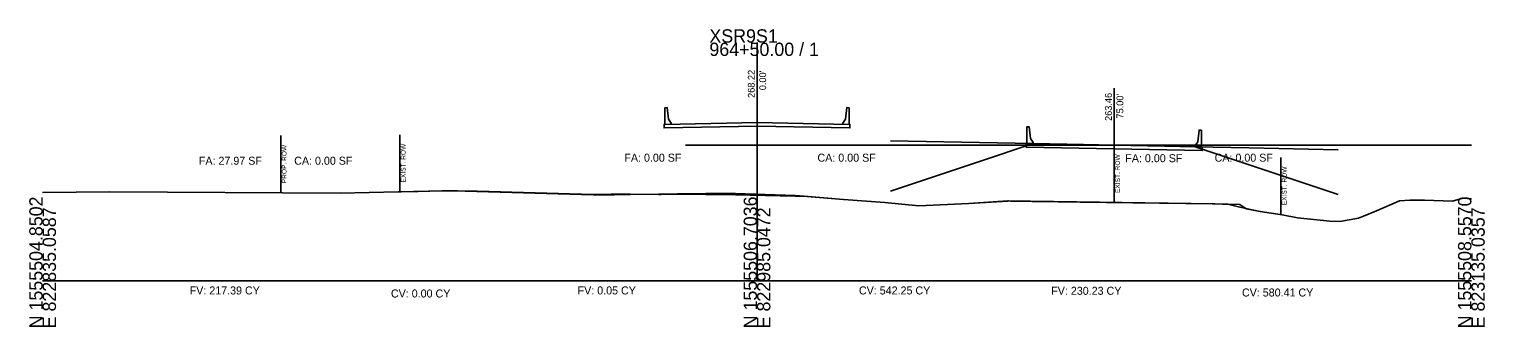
# Model space of a CAD drawing. Extents: x -26 to 823017, y -16 to 1558356.
# Drawn here: x 997.2 to 1302.8, y 3990.3 to 4052.8 of the extents above; entities that cross this region are included whole.
import ezdxf

# ---------------------------------------------------------------- set-up
doc = ezdxf.new("R2010")
doc.units = 0
for name, color, linetype in [('CONST_LV3', 7, 'Continuous'), ('Draft_XS_Grid', 7, 'Continuous'), ('DTM_TEMP_DROP', 7, 'Continuous'), ('DTM_X_GROUND', 7, 'Continuous'), ('XS_CELL', 7, 'Continuous'), ('XS_P_CONCRETE', 7, 'Continuous'), ('XS_P_ROW', 7, 'Continuous'), ('XS_P_TX_CLEARZONE', 7, 'Continuous'), ('XS_SHEET_EW_TX_AREA', 7, 'Continuous'), ('XS_SHEET_EW_TX_VOLUME', 7, 'Continuous'), ('XS_X_ROW', 7, 'Continuous')]:
    doc.layers.add(name, color=color, linetype=linetype)

msp = doc.modelspace()

# ---------------------------------------------------------------- linework, layer by layer
at = {"layer": 'CONST_LV3'}
for points in [[(1178, 4029.4), (1196.69, 4029.03), (1208, 4028.8), (1218.59, 4028.59), (1225, 4028.46), (1235.59, 4028.25), (1242, 4028.12), (1253.31, 4027.9), (1272, 4027.52)], [(1135, 4028.46), (1270.69, 4028.46), (1300, 4028.46)], [(1178, 4018.8), (1196.69, 4025.03), (1208, 4028.8), (1218.59, 4028.59), (1225, 4028.46), (1235.59, 4028.25), (1242, 4028.12), (1253.31, 4024.35), (1272, 4018.12)], [(1000, 4018.55), (1014.1, 4018.69), (1062.49, 4018.4), (1074.65, 4018.64), (1075.26, 4018.66), (1078.83, 4018.75), (1083.81, 4018.89), (1084.26, 4018.9), (1085.24, 4018.88), (1085.42, 4018.88), (1087.17, 4018.85), (1088.71, 4018.82), (1091.26, 4018.75), (1115.61, 4018.02), (1116.22, 4018.03), (1119.39, 4018.07), (1120.02, 4018.07), (1123.35, 4018.11), (1129.29, 4018.2), (1129.91, 4018.2), (1133.34, 4018.23), (1139.25, 4018.32), (1139.85, 4018.32), (1143.34, 4018.35), (1145.45, 4018.29), (1158.01, 4017.92), (1159.9, 4017.75), (1168.15, 4017.05), (1176.81, 4016.42), (1183.98, 4015.75), (1194.49, 4016.24), (1199.14, 4016.53), (1202.6, 4016.73), (1202.79, 4016.75), (1203.23, 4016.74), (1203.92, 4016.73), (1204.53, 4016.72), (1206.18, 4016.7), (1207.81, 4016.67), (1208.62, 4016.66), (1211.26, 4016.62), (1213.18, 4016.6), (1213.94, 4016.58), (1216.27, 4016.55), (1217.83, 4016.53), (1245.57, 4016.13), (1246.01, 4016.12), (1246.12, 4016.12), (1247.77, 4016.09), (1247.89, 4016.08), (1248.84, 4016.07), (1251.36, 4015.48), (1252.69, 4015.17), (1253.99, 4014.86), (1255.67, 4014.57), (1260.28, 4013.82), (1263.51, 4013.2), (1270.27, 4012.54), (1272.39, 4012.44), (1276.27, 4013.17), (1277.36, 4013.55), (1280.07, 4014.71), (1284.92, 4016.77), (1287.11, 4016.92), (1290.19, 4016.92), (1296.02, 4016.73), (1298.18, 4017.32), (1300, 4017.17)]]:
    msp.add_lwpolyline(points, dxfattribs=at)
at = {"layer": 'DTM_X_GROUND'}
for points in [[(1000, 4018.55), (1014.1, 4018.69), (1062.49, 4018.4), (1074.65, 4018.64), (1084.26, 4018.9), (1088.71, 4018.82), (1115.61, 4018.02), (1119.39, 4018.07), (1123.35, 4018.11), (1129.29, 4018.2), (1133.34, 4018.23), (1139.25, 4018.32), (1143.34, 4018.35), (1158.01, 4017.92), (1168.15, 4017.05), (1176.81, 4016.42), (1183.98, 4015.75), (1194.49, 4016.24), (1202.6, 4016.75), (1246.01, 4016.12), (1251.36, 4016.02), (1252.69, 4015.09), (1255.67, 4014.57), (1260.28, 4013.82), (1263.51, 4013.2), (1270.27, 4012.54), (1272.39, 4012.44), (1276.27, 4013.17), (1277.36, 4013.55), (1280.07, 4014.71), (1284.92, 4016.77), (1287.11, 4016.92), (1290.19, 4016.92), (1296.02, 4016.73), (1298.18, 4017.32), (1300, 4017.17)], [(1000, 4018.55), (1014.1, 4018.69), (1062.49, 4018.4), (1074.65, 4018.64), (1084.26, 4018.9), (1088.71, 4018.82), (1115.61, 4018.02), (1119.39, 4018.07), (1123.35, 4018.11), (1129.29, 4018.2), (1133.34, 4018.23), (1139.25, 4018.32), (1143.34, 4018.35), (1158.01, 4017.92), (1168.15, 4017.05), (1176.81, 4016.42), (1183.98, 4015.75), (1194.49, 4016.24), (1199.14, 4016.53), (1202.6, 4016.73), (1202.79, 4016.75), (1203.23, 4016.74), (1203.92, 4016.73), (1204.53, 4016.72), (1206.18, 4016.7), (1207.81, 4016.67), (1208.62, 4016.66), (1211.26, 4016.62), (1213.18, 4016.6), (1213.94, 4016.58), (1216.27, 4016.55), (1217.83, 4016.53), (1245.57, 4016.13), (1246.01, 4016.12), (1246.12, 4016.12), (1247.77, 4016.09), (1247.89, 4016.08), (1248.84, 4016.07), (1251.36, 4015.48), (1252.69, 4015.17), (1253.99, 4014.86), (1255.67, 4014.57), (1260.28, 4013.82), (1263.51, 4013.2), (1270.27, 4012.54), (1272.39, 4012.44), (1276.27, 4013.17), (1277.36, 4013.55), (1280.07, 4014.71), (1284.92, 4016.77), (1287.11, 4016.92), (1290.19, 4016.92), (1296.02, 4016.73), (1298.18, 4017.32), (1300, 4017.17)], [(1000, 4018.55), (1014.1, 4018.69), (1062.49, 4018.4), (1074.65, 4018.64), (1075.26, 4018.66), (1078.83, 4018.75), (1083.81, 4018.85), (1084.26, 4018.85), (1085.24, 4018.85), (1085.42, 4018.88), (1087.17, 4018.86), (1088.71, 4018.84), (1091.26, 4018.81), (1115.61, 4018.14), (1116.22, 4018.13), (1119.39, 4018.16), (1120.02, 4018.16), (1123.35, 4018.19), (1129.29, 4018.12), (1129.91, 4018.12), (1133.34, 4018.15), (1139.25, 4018.08), (1139.85, 4018.07), (1143.34, 4018.1), (1145.45, 4018.07), (1158.01, 4017.78), (1159.9, 4017.75), (1168.15, 4017.05), (1176.81, 4016.42), (1183.98, 4015.75), (1194.49, 4016.24), (1199.14, 4016.53), (1202.6, 4016.73), (1202.79, 4016.75), (1203.23, 4016.74), (1203.92, 4016.73), (1204.53, 4016.72), (1206.18, 4016.7), (1207.81, 4016.67), (1208.62, 4016.66), (1211.26, 4016.62), (1213.18, 4016.6), (1213.94, 4016.58), (1216.27, 4016.55), (1217.83, 4016.53), (1245.57, 4016.13), (1246.01, 4016.12), (1246.12, 4016.12), (1247.77, 4016.09), (1247.89, 4016.08), (1248.84, 4016.07), (1251.36, 4015.48), (1252.69, 4015.17), (1253.99, 4014.86), (1255.67, 4014.57), (1260.28, 4013.82), (1263.51, 4013.2), (1270.27, 4012.54), (1272.39, 4012.44), (1276.27, 4013.17), (1277.36, 4013.55), (1280.07, 4014.71), (1284.92, 4016.77), (1287.11, 4016.92), (1290.19, 4016.92), (1296.02, 4016.73), (1298.18, 4017.32), (1300, 4017.17)]]:
    msp.add_lwpolyline(points, dxfattribs=at)
at = {"layer": 'XS_CELL'}
for p, q in [((1150, 4000), (1150, 4050)), ((1000, 4000), (1150, 4000)), ((1150, 4000), (1300, 4000))]:
    msp.add_line(p, q, dxfattribs=at)
at = {"layer": 'XS_P_CONCRETE'}
for points in [[(1132, 4032.86), (1132, 4033.11), (1131.42, 4033.94), (1131.17, 4036.36), (1130.67, 4036.33), (1130.67, 4032.83), (1132, 4032.86)], [(1168, 4032.86), (1168, 4033.11), (1168.58, 4033.94), (1168.83, 4036.36), (1169.33, 4036.33), (1169.33, 4032.83), (1168, 4032.86)], [(1150, 4033.22), (1169.33, 4032.83), (1169.5, 4032.83), (1169.5, 4032.08), (1150, 4032.47), (1130.5, 4032.08), (1130.5, 4032.83), (1130.67, 4032.83), (1150, 4033.22)], [(1206.67, 4028.83), (1206.67, 4032.33), (1207.17, 4032.3), (1207.42, 4029.88), (1208, 4029.05), (1208, 4028.8), (1206.67, 4028.83)], [(1243.33, 4028.09), (1243.33, 4031.59), (1242.83, 4031.62), (1242.58, 4029.2), (1242, 4028.37), (1242, 4028.12), (1243.33, 4028.09)], [(1225, 4028.46), (1243.33, 4028.09), (1243.5, 4028.09), (1243.5, 4027.34), (1225, 4027.71), (1206.5, 4028.08), (1206.5, 4028.83), (1206.67, 4028.83), (1225, 4028.46)]]:
    msp.add_lwpolyline(points, dxfattribs=at)
at = {"layer": 'XS_P_ROW'}
msp.add_line((1050, 4018.48), (1050, 4030.48), dxfattribs=at)
at = {"layer": 'XS_P_TX_CLEARZONE'}
for p, q in [((1150, 4033.22), (1150, 4045.22)), ((1225, 4028.46), (1225, 4040.46))]:
    msp.add_line(p, q, dxfattribs=at)
at = {"layer": 'XS_X_ROW'}
for p, q in [((1075, 4018.65), (1075, 4030.65)), ((1225, 4016.42), (1225, 4028.42)), ((1260, 4013.86), (1260, 4025.86))]:
    msp.add_line(p, q, dxfattribs=at)

# ---------------------------------------------------------------- texts
at = {"layer": 'Draft_XS_Grid'}
msp.add_text('-', height=0.0001, dxfattribs=at).set_placement((1000, 4000))
at = {"layer": 'DTM_TEMP_DROP'}
for p in [(1149.92, 4033.1), (1224.92, 4028.34)]:
    msp.add_text('X', height=0.24, dxfattribs=at).set_placement(p)
at = {"layer": 'XS_CELL'}
for s, p in [('XSR9S1', (1140, 4050)), ('964+50.00 / 1', (1140, 4047.2))]:
    msp.add_text(s, height=2.8, dxfattribs=at).set_placement(p)
for s, p in [('N 1555504.8502', (1000, 3990)), ('N 1555506.7036', (1150, 3990)), ('N 1555508.5570', (1300, 3990)), ('E 822835.0587', (1002.8, 3990)), ('E 822985.0472', (1152.8, 3990)), ('E 823135.0357', (1302.8, 3990))]:
    msp.add_text(s, height=2.8, rotation=90, dxfattribs=at).set_placement(p)
at = {"layer": 'XS_P_ROW'}
msp.add_text('PROP. ROW', height=1, rotation=90, dxfattribs=at).set_placement((1051.2, 4020.48))
at = {"layer": 'XS_P_TX_CLEARZONE'}
for s, p in [('268.22', (1149.52, 4038.4)), ("0.00'", (1151.92, 4040.01)), ('263.46', (1224.52, 4033.56)), ("75.00'", (1226.92, 4034.07))]:
    msp.add_text(s, height=1.44, rotation=90, dxfattribs=at).set_placement(p)
at = {"layer": 'XS_SHEET_EW_TX_AREA'}
for s, p in [('FA: 27.97 SF', (1032.8, 4024.36)), ('CA: 0.00 SF', (1052.82, 4024.36)), ('FA: 0.00 SF', (1122.15, 4025)), ('CA: 0.00 SF', (1162.7, 4025)), ('FA: 0.00 SF', (1227.33, 4024.89)), ('CA: 0.00 SF', (1246.09, 4025))]:
    msp.add_text(s, height=1.68, dxfattribs=at).set_placement(p)
at = {"layer": 'XS_SHEET_EW_TX_VOLUME'}
for s, p in [('FV: 217.39 CY', (1030.87, 3997.12)), ('FV: 0.05 CY', (1112.33, 3997.12)), ('CV: 542.25 CY', (1171.4, 3997.12)), ('FV: 230.23 CY', (1211.78, 3997.05)), ('CV: 580.41 CY', (1251.83, 3996.69)), ('CV: 0.00 CY', (1073.13, 3996.48))]:
    msp.add_text(s, height=1.68, dxfattribs=at).set_placement(p)
at = {"layer": 'XS_X_ROW'}
for p in [(1076.2, 4020.65), (1226.2, 4018.42), (1261.2, 4015.86)]:
    msp.add_text('EXIST. ROW', height=1, rotation=90, dxfattribs=at).set_placement(p)

doc.saveas('drawing.dxf')
